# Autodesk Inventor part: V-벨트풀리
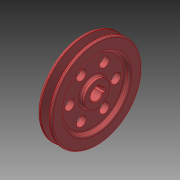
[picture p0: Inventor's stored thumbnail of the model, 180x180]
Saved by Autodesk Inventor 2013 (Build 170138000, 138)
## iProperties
Created: 2010-03
Part Number: V-벨트풀리
Document SubType Name: Modeling
Designer: Administrator
Density: 1 g/cm^3
Material: 스테인리스강
Author: Administrator
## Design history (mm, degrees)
sketch "스케치1"
  geometry: L1 (-10, 0)-(10, 0); L2 (10, 0)-(10, 65); L3 (-10, 65)-(-10, 0); L4 (10, 19)-(10, 0); L5 (-10, 65)-(-6.062, 65); L6 (-6.062, 65)-(-2.001, 52.5); L7 (2.001, 52.5)-(6.062, 65); L8 (6.062, 65)-(10, 65); L9 (-2.001, 52.5)-(2.001, 52.5); L10 (-10, 47)-(-4, 47); L11 (-4, 47)-(-4, 18); L12 (-4, 18)-(-10, 18); L13 (-10, 18)-(-10, 47); L14 (10, 47)-(4, 47); L15 (4, 47)-(4, 18); L16 (4, 18)-(10, 18); L17 (10, 18)-(10, 47); 5 further points
  constraints: 34 end point, 6 collinear, 6 horizontal, 5 parallel, 4 point on line, 3 perpendicular, 2 midpoint, 1 coincident, 1 horizontal alignment, 1 vertical alignment
  dimensions: "d0" = 121 diameter of point (-4.6, 60.5) L1; "d1" = 4.5 distance from line of L5 point (-4.6, 60.5); "d2" = 8 distance from line of L9 point (-4.6, 60.5); "d3" = 9.2 distance of point (-4.6, 60.5) point (4.6, 60.5); "d4" = 36 deg angle of L7 L6; "d5" = 10 distance from line of point (0, 52.5) L3; "d8" = 6 distance of L14.start L14.end; "d10" = 29 distance of L14.end L15.end; "d29" = 36 diameter of L16 L1
revolve "회전1" sketch "스케치1" stored, may be unused: angle "d11" = 90 deg
fillet "모깎기1" dims "d12" = 2, "d13" = 1, "d14" = 0.5
fillet "모깎기2" dims "d15" = 3
sketch "스케치2"
  geometry: L1 (-3, 8.485)-(3, 8.485); L2 (3, 8.485)-(3, 11.8); L3 (3, 11.8)-(-3, 11.8); L4 (-3, 11.8)-(-3, 8.485); C1 r 18 at (0, 0) reference; A1 r 9 centre (0, 0) between (-3, 8.485) and (3, 8.485)
  constraints: 8 end point, 2 parallel, 2 point on circle, 1 centre point, 1 concentric, 1 horizontal, 1 perpendicular
  dimensions: "d16" = 18 diameter of A1; "d19" = 2.8 distance edge to line of A1 L3; "d20" = 6 distance of L2.end L3.end
extrude "돌출1" cut sketch "스케치2" stored distance "d17" = 10; taper "d18" = 0 deg
chamfer "모따기1" distance "d30" = 1; stored, may be unused: second distance "d31" = 2, angle "d32" = 45 deg
sketch "스케치4" dims "d33" = 66
  geometry: C1 r 7 at (0, 33); 2 further points
  constraints: 2 vertical alignment, 1 centre point, 1 coincident, 2 other
  dimensions: "d34" = 14 diameter of C1
extrude "돌출2" cut sketch "스케치4" stored distance "d35" = 10; taper "d36" = 0 deg
node "솔리드1"
pattern_circular "원형 패턴1" dims angle "d38" = 360 deg
